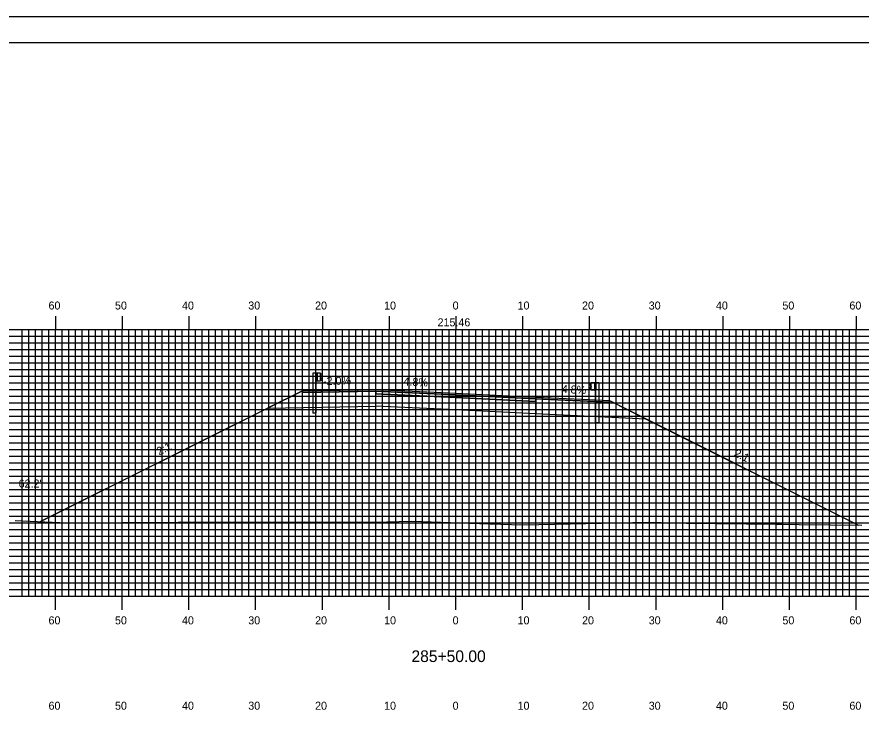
# Model space of a CAD drawing. Extents: x 1812161 to 1812504, y 442591 to 442811.
# Drawn here: x 1812260.7 to 1812387.2, y 442706.2 to 442810.5 of the extents above; entities that cross this region are included whole.
import ezdxf

# ---------------------------------------------------------------- set-up
doc = ezdxf.new("R2010")
doc.units = 0
for name, color, linetype in [('ANNOTATION', 7, 'Continuous'), ('BORDER', 7, 'Continuous'), ('D_Guardrail_Beam_Lt', 7, 'Continuous'), ('D_Guardrail_Beam_Rt', 7, 'Continuous'), ('D_Roadway_Centerline', 7, 'Continuous'), ('D_Roadway_Centerline_Text', 7, 'Continuous'), ('D_Roadway_Edge_Shoulder', 7, 'Continuous'), ('D_Roadway_Edge_TW', 7, 'Continuous'), ('D_Roadway_Pavement', 7, 'Continuous'), ('D_Roadway_SlopeLines', 7, 'Continuous'), ('D_Roadway_SubGrade', 7, 'Continuous'), ('D_Text_Standard', 7, 'Continuous'), ('H_V ANNOTATION', 7, 'Continuous'), ('MAJOR', 7, 'Continuous'), ('MINOR', 7, 'Continuous'), ('PLOT BOUNDARY', 7, 'Continuous'), ('S_Roadway_Centerline', 7, 'Continuous')]:
    doc.layers.add(name, color=color, linetype=linetype)

msp = doc.modelspace()

# ---------------------------------------------------------------- linework, layer by layer
at = {"layer": 'BORDER'}
msp.add_lwpolyline([(1812176.83, 442596.67), (1812496.83, 442596.67), (1812496.83, 442806.67), (1812176.83, 442806.67)], close=True, dxfattribs=at)
at = {"layer": 'D_Guardrail_Beam_Lt'}
for p, q in [((1812305, 442757.12), (1812305, 442751.12)), ((1812305.47, 442757.12), (1812305, 442757.12)), ((1812306.16, 442757.12), (1812305.47, 442757.12)), ((1812305.47, 442757.12), (1812305.47, 442755.96)), ((1812305.53, 442757.12), (1812305.53, 442755.96)), ((1812305.64, 442757.12), (1812305.64, 442755.96)), ((1812306.16, 442755.96), (1812306.16, 442757.12)), ((1812305.47, 442755.96), (1812306.16, 442755.96)), ((1812305.49, 442751.12), (1812305.49, 442755.96)), ((1812306.16, 442757.04), (1812306.23, 442757.02)), ((1812306.16, 442756.57), (1812306.16, 442756.5)), ((1812306.23, 442756.05), (1812306.16, 442756.04)), ((1812306.39, 442756.78), (1812306.2, 442756.64)), ((1812306.2, 442756.44), (1812306.39, 442756.3)), ((1812306.25, 442757.02), (1812306.39, 442756.92)), ((1812306.39, 442756.16), (1812306.25, 442756.06)), ((1812305.49, 442751.12), (1812305, 442751.12))]:
    msp.add_line(p, q, dxfattribs=at)
for centre, major_axis, start_param, end_param in [((1812306.24, 442756.57), (-0.0789, 0), 5.323254, 6.283185), ((1812306.24, 442756.5), (-0.0789, 0), 6.283185, 7.243116), ((1812306.22, 442756.98), (0.0417, 0), 0.959931, 1.376053), ((1812306.22, 442756.09), (0.0417, 0), 4.907132, 5.323254), ((1812306.34, 442756.85), (0.0877, 0), 5.323254, 7.243116), ((1812306.34, 442756.23), (0.0877, 0), 5.323254, 7.243116)]:
    msp.add_ellipse(centre, major_axis=major_axis, ratio=0.995501, start_param=start_param, end_param=end_param, dxfattribs=at)
at = {"layer": 'D_Guardrail_Beam_Rt'}
for p, q in [((1812346.61, 442755.64), (1812346.47, 442755.54)), ((1812346.47, 442755.4), (1812346.66, 442755.26)), ((1812346.66, 442755.06), (1812346.47, 442754.93)), ((1812346.47, 442754.78), (1812346.61, 442754.68)), ((1812346.7, 442755.66), (1812346.63, 442755.65)), ((1812346.63, 442754.68), (1812346.7, 442754.66)), ((1812346.7, 442755.75), (1812347.39, 442755.75)), ((1812346.7, 442754.58), (1812346.7, 442755.75)), ((1812346.7, 442755.2), (1812346.7, 442755.13)), ((1812347.39, 442754.58), (1812346.7, 442754.58)), ((1812347.22, 442755.75), (1812347.22, 442754.58)), ((1812347.32, 442755.75), (1812347.32, 442754.58)), ((1812347.37, 442749.75), (1812347.37, 442754.58)), ((1812347.39, 442755.75), (1812347.86, 442755.75)), ((1812347.39, 442755.75), (1812347.39, 442754.58)), ((1812347.86, 442755.75), (1812347.86, 442749.75)), ((1812347.37, 442749.75), (1812347.86, 442749.75))]:
    msp.add_line(p, q, dxfattribs=at)
for centre, major_axis, start_param, end_param in [((1812346.52, 442755.47), (-0.0877, 0), 5.323254, 7.243116), ((1812346.52, 442754.86), (-0.0877, 0), 5.323254, 7.243116), ((1812346.63, 442755.61), (-0.0417, 0), 4.907132, 5.323254), ((1812346.63, 442754.72), (-0.0417, 0), 0.959931, 1.376053), ((1812346.62, 442755.2), (0.0789, 0), 0, 0.959931), ((1812346.62, 442755.13), (0.0789, 0), 5.323254, 6.283185)]:
    msp.add_ellipse(centre, major_axis=major_axis, ratio=0.995501, start_param=start_param, end_param=end_param, dxfattribs=at)
at = {"layer": 'D_Roadway_Centerline'}
msp.add_lwpolyline([(1812264.21, 442734.87), (1812298.22, 442751.88), (1812303.43, 442754.48), (1812306.43, 442754.54), (1812314.43, 442754.7), (1812326.43, 442754.12), (1812338.43, 442753.55), (1812346.43, 442753.16), (1812349.43, 442753.02), (1812354.96, 442750.25), (1812386.74, 442734.36)], dxfattribs=at)
at = {"layer": 'D_Roadway_Edge_Shoulder'}
for points in [[(1812314.43, 442754.7), (1812306.43, 442754.54), (1812306.43, 442754.54), (1812303.43, 442754.48), (1812303.43, 442754.23), (1812314.43, 442754.45)], [(1812338.43, 442753.55), (1812346.43, 442753.16), (1812346.43, 442753.16), (1812349.43, 442753.02), (1812349.43, 442752.77), (1812338.43, 442753.3)]]:
    msp.add_lwpolyline(points, close=True, dxfattribs=at)
at = {"layer": 'D_Roadway_Edge_TW'}
msp.add_lwpolyline([(1812314.43, 442754.45), (1812314.43, 442754.7), (1812326.43, 442754.12), (1812338.43, 442753.55), (1812338.43, 442753.3), (1812326.43, 442753.87)], close=True, dxfattribs=at)
at = {"layer": 'D_Roadway_Pavement'}
msp.add_lwpolyline([(1812314.43, 442754.03), (1812314.43, 442754.45), (1812326.43, 442753.87), (1812338.43, 442753.3), (1812338.43, 442752.88), (1812326.43, 442753.46)], close=True, dxfattribs=at)
for points in [[(1812314.43, 442754.45), (1812314.43, 442754.03)], [(1812338.43, 442753.3), (1812338.43, 442752.88)]]:
    msp.add_lwpolyline(points, dxfattribs=at)
at = {"layer": 'D_Roadway_SlopeLines'}
for points in [[(1812303.43, 442754.48), (1812264.21, 442734.87)], [(1812349.43, 442753.02), (1812386.74, 442734.36)]]:
    msp.add_lwpolyline(points, dxfattribs=at)
at = {"layer": 'D_Roadway_SubGrade'}
for points in [[(1812314.43, 442754.03), (1812314.43, 442754.45), (1812303.43, 442754.23), (1812303.43, 442754.48), (1812298.22, 442751.88), (1812314.43, 442752.2)], [(1812314.43, 442752.2), (1812314.43, 442754.45), (1812314.43, 442754.03), (1812326.43, 442753.46), (1812338.43, 442752.88), (1812338.43, 442753.3), (1812338.43, 442751.05), (1812326.43, 442751.62)], [(1812338.43, 442752.88), (1812338.43, 442753.3), (1812349.43, 442752.77), (1812349.43, 442753.02), (1812354.96, 442750.25), (1812338.43, 442751.05)]]:
    msp.add_lwpolyline(points, close=True, dxfattribs=at)
at = {"layer": 'MAJOR'}
for p, q in [((1812266.43, 442765.67), (1812266.43, 442763.67)), ((1812276.43, 442765.67), (1812276.43, 442763.67)), ((1812286.43, 442765.67), (1812286.43, 442763.67)), ((1812296.43, 442765.67), (1812296.43, 442763.67)), ((1812306.43, 442765.67), (1812306.43, 442763.67)), ((1812316.43, 442765.67), (1812316.43, 442763.67)), ((1812326.43, 442765.67), (1812326.43, 442763.67)), ((1812336.43, 442765.67), (1812336.43, 442763.67)), ((1812346.43, 442765.67), (1812346.43, 442763.67)), ((1812356.43, 442765.67), (1812356.43, 442763.67)), ((1812366.43, 442765.67), (1812366.43, 442763.67)), ((1812376.43, 442765.67), (1812376.43, 442763.67)), ((1812386.43, 442765.67), (1812386.43, 442763.67)), ((1812186.43, 442763.67), (1812466.43, 442763.67)), ((1812186.43, 442763.67), (1812466.43, 442763.67)), ((1812266.43, 442723.67), (1812266.43, 442763.67)), ((1812276.43, 442723.67), (1812276.43, 442763.67)), ((1812286.43, 442723.67), (1812286.43, 442763.67)), ((1812296.43, 442723.67), (1812296.43, 442763.67)), ((1812306.43, 442723.67), (1812306.43, 442763.67)), ((1812316.43, 442723.67), (1812316.43, 442763.67)), ((1812326.43, 442723.67), (1812326.43, 442763.67)), ((1812336.43, 442723.67), (1812336.43, 442763.67)), ((1812346.43, 442723.67), (1812346.43, 442763.67)), ((1812356.43, 442723.67), (1812356.43, 442763.67)), ((1812366.43, 442723.67), (1812366.43, 442763.67)), ((1812376.43, 442723.67), (1812376.43, 442763.67)), ((1812386.43, 442723.67), (1812386.43, 442763.67)), ((1812186.43, 442758.67), (1812466.43, 442758.67)), ((1812186.43, 442753.67), (1812466.43, 442753.67)), ((1812186.43, 442748.67), (1812466.43, 442748.67)), ((1812186.43, 442743.67), (1812466.43, 442743.67)), ((1812186.43, 442738.67), (1812466.43, 442738.67)), ((1812186.43, 442733.67), (1812466.43, 442733.67)), ((1812186.43, 442728.67), (1812466.43, 442728.67)), ((1812186.43, 442723.67), (1812466.43, 442723.67)), ((1812186.43, 442723.67), (1812466.43, 442723.67)), ((1812266.43, 442721.66), (1812266.43, 442723.67)), ((1812276.43, 442721.66), (1812276.43, 442723.67)), ((1812286.43, 442721.66), (1812286.43, 442723.67)), ((1812296.43, 442721.66), (1812296.43, 442723.67)), ((1812306.43, 442721.66), (1812306.43, 442723.67)), ((1812316.43, 442721.66), (1812316.43, 442723.67)), ((1812326.43, 442721.66), (1812326.43, 442723.67)), ((1812336.43, 442721.66), (1812336.43, 442723.67)), ((1812346.43, 442721.66), (1812346.43, 442723.67)), ((1812356.43, 442721.66), (1812356.43, 442723.67)), ((1812366.43, 442721.66), (1812366.43, 442723.67)), ((1812376.43, 442721.66), (1812376.43, 442723.67)), ((1812386.43, 442721.66), (1812386.43, 442723.67))]:
    msp.add_line(p, q, dxfattribs=at)
at = {"layer": 'MINOR'}
for p, q in [((1812261.43, 442723.67), (1812261.43, 442763.67)), ((1812262.43, 442723.67), (1812262.43, 442763.67)), ((1812263.43, 442723.67), (1812263.43, 442763.67)), ((1812264.43, 442723.67), (1812264.43, 442763.67)), ((1812265.43, 442723.67), (1812265.43, 442763.67)), ((1812267.43, 442723.67), (1812267.43, 442763.67)), ((1812268.43, 442723.67), (1812268.43, 442763.67)), ((1812269.43, 442723.67), (1812269.43, 442763.67)), ((1812270.43, 442723.67), (1812270.43, 442763.67)), ((1812271.43, 442723.67), (1812271.43, 442763.67)), ((1812272.43, 442723.67), (1812272.43, 442763.67)), ((1812273.43, 442723.67), (1812273.43, 442763.67)), ((1812274.43, 442723.67), (1812274.43, 442763.67)), ((1812275.43, 442723.67), (1812275.43, 442763.67)), ((1812277.43, 442723.67), (1812277.43, 442763.67)), ((1812278.43, 442723.67), (1812278.43, 442763.67)), ((1812279.43, 442723.67), (1812279.43, 442763.67)), ((1812280.43, 442723.67), (1812280.43, 442763.67)), ((1812281.43, 442723.67), (1812281.43, 442763.67)), ((1812282.43, 442723.67), (1812282.43, 442763.67)), ((1812283.43, 442723.67), (1812283.43, 442763.67)), ((1812284.43, 442723.67), (1812284.43, 442763.67)), ((1812285.43, 442723.67), (1812285.43, 442763.67)), ((1812287.43, 442723.67), (1812287.43, 442763.67)), ((1812288.43, 442723.67), (1812288.43, 442763.67)), ((1812289.43, 442723.67), (1812289.43, 442763.67)), ((1812290.43, 442723.67), (1812290.43, 442763.67)), ((1812291.43, 442723.67), (1812291.43, 442763.67)), ((1812292.43, 442723.67), (1812292.43, 442763.67)), ((1812293.43, 442723.67), (1812293.43, 442763.67)), ((1812294.43, 442723.67), (1812294.43, 442763.67)), ((1812295.43, 442723.67), (1812295.43, 442763.67)), ((1812297.43, 442723.67), (1812297.43, 442763.67)), ((1812298.43, 442723.67), (1812298.43, 442763.67)), ((1812299.43, 442723.67), (1812299.43, 442763.67)), ((1812300.43, 442723.67), (1812300.43, 442763.67)), ((1812301.43, 442723.67), (1812301.43, 442763.67)), ((1812302.43, 442723.67), (1812302.43, 442763.67)), ((1812303.43, 442723.67), (1812303.43, 442763.67)), ((1812304.43, 442723.67), (1812304.43, 442763.67)), ((1812305.43, 442723.67), (1812305.43, 442763.67)), ((1812307.43, 442723.67), (1812307.43, 442763.67)), ((1812308.43, 442723.67), (1812308.43, 442763.67)), ((1812309.43, 442723.67), (1812309.43, 442763.67)), ((1812310.43, 442723.67), (1812310.43, 442763.67)), ((1812311.43, 442723.67), (1812311.43, 442763.67)), ((1812312.43, 442723.67), (1812312.43, 442763.67)), ((1812313.43, 442723.67), (1812313.43, 442763.67)), ((1812314.43, 442723.67), (1812314.43, 442763.67)), ((1812315.43, 442723.67), (1812315.43, 442763.67)), ((1812317.43, 442723.67), (1812317.43, 442763.67)), ((1812318.43, 442723.67), (1812318.43, 442763.67)), ((1812319.43, 442723.67), (1812319.43, 442763.67)), ((1812320.43, 442723.67), (1812320.43, 442763.67)), ((1812321.43, 442723.67), (1812321.43, 442763.67)), ((1812322.43, 442723.67), (1812322.43, 442763.67)), ((1812323.43, 442723.67), (1812323.43, 442763.67)), ((1812324.43, 442723.67), (1812324.43, 442763.67)), ((1812325.43, 442723.67), (1812325.43, 442763.67)), ((1812327.43, 442723.67), (1812327.43, 442763.67)), ((1812328.43, 442723.67), (1812328.43, 442763.67)), ((1812329.43, 442723.67), (1812329.43, 442763.67)), ((1812330.43, 442723.67), (1812330.43, 442763.67)), ((1812331.43, 442723.67), (1812331.43, 442763.67)), ((1812332.43, 442723.67), (1812332.43, 442763.67)), ((1812333.43, 442723.67), (1812333.43, 442763.67)), ((1812334.43, 442723.67), (1812334.43, 442763.67)), ((1812335.43, 442723.67), (1812335.43, 442763.67)), ((1812337.43, 442723.67), (1812337.43, 442763.67)), ((1812338.43, 442723.67), (1812338.43, 442763.67)), ((1812339.43, 442723.67), (1812339.43, 442763.67)), ((1812340.43, 442723.67), (1812340.43, 442763.67)), ((1812341.43, 442723.67), (1812341.43, 442763.67)), ((1812342.43, 442723.67), (1812342.43, 442763.67)), ((1812343.43, 442723.67), (1812343.43, 442763.67)), ((1812344.43, 442723.67), (1812344.43, 442763.67)), ((1812345.43, 442723.67), (1812345.43, 442763.67)), ((1812347.43, 442723.67), (1812347.43, 442763.67)), ((1812348.43, 442723.67), (1812348.43, 442763.67)), ((1812349.43, 442723.67), (1812349.43, 442763.67)), ((1812350.43, 442723.67), (1812350.43, 442763.67)), ((1812351.43, 442723.67), (1812351.43, 442763.67)), ((1812352.43, 442723.67), (1812352.43, 442763.67)), ((1812353.43, 442723.67), (1812353.43, 442763.67)), ((1812354.43, 442723.67), (1812354.43, 442763.67)), ((1812355.43, 442723.67), (1812355.43, 442763.67)), ((1812357.43, 442723.67), (1812357.43, 442763.67)), ((1812358.43, 442723.67), (1812358.43, 442763.67)), ((1812359.43, 442723.67), (1812359.43, 442763.67)), ((1812360.43, 442723.67), (1812360.43, 442763.67)), ((1812361.43, 442723.67), (1812361.43, 442763.67)), ((1812362.43, 442723.67), (1812362.43, 442763.67)), ((1812363.43, 442723.67), (1812363.43, 442763.67)), ((1812364.43, 442723.67), (1812364.43, 442763.67)), ((1812365.43, 442723.67), (1812365.43, 442763.67)), ((1812367.43, 442723.67), (1812367.43, 442763.67)), ((1812368.43, 442723.67), (1812368.43, 442763.67)), ((1812369.43, 442723.67), (1812369.43, 442763.67)), ((1812370.43, 442723.67), (1812370.43, 442763.67)), ((1812371.43, 442723.67), (1812371.43, 442763.67)), ((1812372.43, 442723.67), (1812372.43, 442763.67)), ((1812373.43, 442723.67), (1812373.43, 442763.67)), ((1812374.43, 442723.67), (1812374.43, 442763.67)), ((1812375.43, 442723.67), (1812375.43, 442763.67)), ((1812377.43, 442723.67), (1812377.43, 442763.67)), ((1812378.43, 442723.67), (1812378.43, 442763.67)), ((1812379.43, 442723.67), (1812379.43, 442763.67)), ((1812380.43, 442723.67), (1812380.43, 442763.67)), ((1812381.43, 442723.67), (1812381.43, 442763.67)), ((1812382.43, 442723.67), (1812382.43, 442763.67)), ((1812383.43, 442723.67), (1812383.43, 442763.67)), ((1812384.43, 442723.67), (1812384.43, 442763.67)), ((1812385.43, 442723.67), (1812385.43, 442763.67)), ((1812186.43, 442762.67), (1812466.43, 442762.67)), ((1812186.43, 442761.67), (1812466.43, 442761.67)), ((1812186.43, 442760.67), (1812466.43, 442760.67)), ((1812186.43, 442759.67), (1812466.43, 442759.67)), ((1812186.43, 442757.67), (1812466.43, 442757.67)), ((1812186.43, 442756.67), (1812466.43, 442756.67)), ((1812186.43, 442755.67), (1812466.43, 442755.67)), ((1812186.43, 442754.67), (1812466.43, 442754.67)), ((1812186.43, 442752.67), (1812466.43, 442752.67)), ((1812186.43, 442751.67), (1812466.43, 442751.67)), ((1812186.43, 442750.67), (1812466.43, 442750.67)), ((1812186.43, 442749.67), (1812466.43, 442749.67)), ((1812186.43, 442747.67), (1812466.43, 442747.67)), ((1812186.43, 442746.67), (1812466.43, 442746.67)), ((1812186.43, 442745.67), (1812466.43, 442745.67)), ((1812186.43, 442744.67), (1812466.43, 442744.67)), ((1812186.43, 442742.67), (1812466.43, 442742.67)), ((1812186.43, 442741.67), (1812466.43, 442741.67)), ((1812186.43, 442740.67), (1812466.43, 442740.67)), ((1812186.43, 442739.67), (1812466.43, 442739.67)), ((1812186.43, 442737.67), (1812466.43, 442737.67)), ((1812186.43, 442736.67), (1812466.43, 442736.67)), ((1812186.43, 442735.67), (1812466.43, 442735.67)), ((1812186.43, 442734.67), (1812466.43, 442734.67)), ((1812186.43, 442732.67), (1812466.43, 442732.67)), ((1812186.43, 442731.67), (1812466.43, 442731.67)), ((1812186.43, 442730.67), (1812466.43, 442730.67)), ((1812186.43, 442729.67), (1812466.43, 442729.67)), ((1812186.43, 442727.67), (1812466.43, 442727.67)), ((1812186.43, 442726.67), (1812466.43, 442726.67)), ((1812186.43, 442725.67), (1812466.43, 442725.67)), ((1812186.43, 442724.67), (1812466.43, 442724.67))]:
    msp.add_line(p, q, dxfattribs=at)
at = {"layer": 'PLOT BOUNDARY'}
msp.add_lwpolyline([(1812160.64, 442590.55), (1812500.64, 442590.55), (1812500.64, 442810.55), (1812160.64, 442810.55)], close=True, dxfattribs=at)
at = {"layer": 'S_Roadway_Centerline'}
msp.add_lwpolyline([(1812260.38, 442735.04), (1812268.2, 442734.7), (1812284.82, 442734.81), (1812285.13, 442734.82), (1812285.57, 442734.81), (1812303.79, 442734.85), (1812314.19, 442734.8), (1812319.84, 442734.92), (1812329.96, 442734.57), (1812336.37, 442734.37), (1812338.87, 442734.42), (1812343.54, 442734.52), (1812355.29, 442734.8), (1812360.97, 442734.64), (1812374.48, 442734.49), (1812375.4, 442734.48), (1812377.85, 442734.45), (1812387.27, 442734.36)], dxfattribs=at)

# ---------------------------------------------------------------- texts
at = {"layer": 'ANNOTATION'}
for s, rotation, p in [('-2.0%', 1.1458, (1812306.54, 442755.34)), ('4.8%', 357.2519, (1812318.56, 442755.3)), ('-4.8%', 357.2519, (1812341.74, 442754.19)), ('2:1', 26.5651, (1812281.97, 442744.78)), ('2:1', 333.4349, (1812368.02, 442744.76))]:
    msp.add_text(s, height=1.2, rotation=rotation, dxfattribs=at).set_placement(p)
at = {"layer": 'D_Roadway_Centerline'}
for s, p in [('C', (1812326.42, 442754.12)), ('L', (1812326.43, 442754.12))]:
    msp.add_text(s, height=0.0146, dxfattribs=at).set_placement(p)
at = {"layer": 'D_Roadway_Centerline_Text'}
msp.add_text('215.46', height=1.2, dxfattribs=at).set_placement((1812323.69, 442764.15))
at = {"layer": 'D_Text_Standard'}
msp.add_text("62.2'", height=1.2, dxfattribs=at).set_placement((1812260.92, 442739.98))
at = {"layer": 'H_V ANNOTATION'}
for s, height, p in [('60', 1.2, (1812265.4, 442766.67)), ('50', 1.2, (1812275.36, 442766.67)), ('40', 1.2, (1812285.4, 442766.67)), ('30', 1.2, (1812295.33, 442766.67)), ('20', 1.2, (1812305.34, 442766.67)), ('10', 1.2, (1812315.68, 442766.67)), ('0', 1.2, (1812325.95, 442766.67)), ('10', 1.2, (1812335.68, 442766.67)), ('20', 1.2, (1812345.34, 442766.67)), ('30', 1.2, (1812355.33, 442766.67)), ('40', 1.2, (1812365.4, 442766.67)), ('50', 1.2, (1812375.36, 442766.67)), ('60', 1.2, (1812385.4, 442766.67)), ('60', 1.2, (1812265.4, 442719.47)), ('50', 1.2, (1812275.36, 442719.47)), ('40', 1.2, (1812285.4, 442719.47)), ('30', 1.2, (1812295.33, 442719.47)), ('20', 1.2, (1812305.34, 442719.47)), ('10', 1.2, (1812315.68, 442719.47)), ('0', 1.2, (1812325.95, 442719.47)), ('10', 1.2, (1812335.68, 442719.47)), ('20', 1.2, (1812345.34, 442719.47)), ('30', 1.2, (1812355.33, 442719.47)), ('40', 1.2, (1812365.4, 442719.47)), ('50', 1.2, (1812375.36, 442719.47)), ('60', 1.2, (1812385.4, 442719.47)), ('285+50.00', 1.75, (1812319.78, 442713.82)), ('60', 1.2, (1812265.4, 442706.67)), ('50', 1.2, (1812275.36, 442706.67)), ('40', 1.2, (1812285.4, 442706.67)), ('30', 1.2, (1812295.33, 442706.67)), ('20', 1.2, (1812305.34, 442706.67)), ('10', 1.2, (1812315.68, 442706.67)), ('0', 1.2, (1812325.95, 442706.67)), ('10', 1.2, (1812335.68, 442706.67)), ('20', 1.2, (1812345.34, 442706.67)), ('30', 1.2, (1812355.33, 442706.67)), ('40', 1.2, (1812365.4, 442706.67)), ('50', 1.2, (1812375.36, 442706.67)), ('60', 1.2, (1812385.4, 442706.67))]:
    msp.add_text(s, height=height, dxfattribs=at).set_placement(p)

doc.saveas('drawing.dxf')
